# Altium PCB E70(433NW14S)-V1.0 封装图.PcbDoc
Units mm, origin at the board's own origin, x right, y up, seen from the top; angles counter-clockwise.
Board outline 26 x 16 mm, 2 copper layers (Top Layer, Bottom Layer); 5 components, 52 nets, 42 pads, 0 vias.
Unrouted connection lines stored in the file: 4.
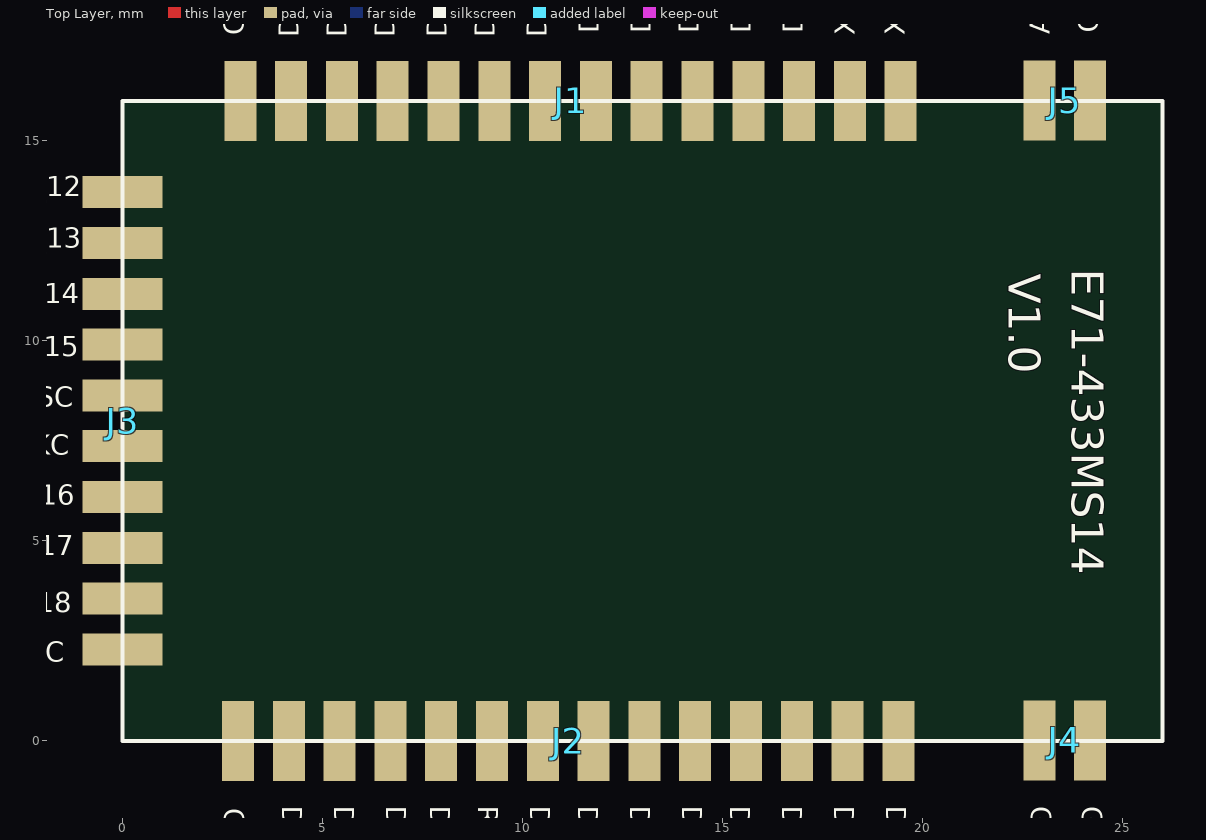
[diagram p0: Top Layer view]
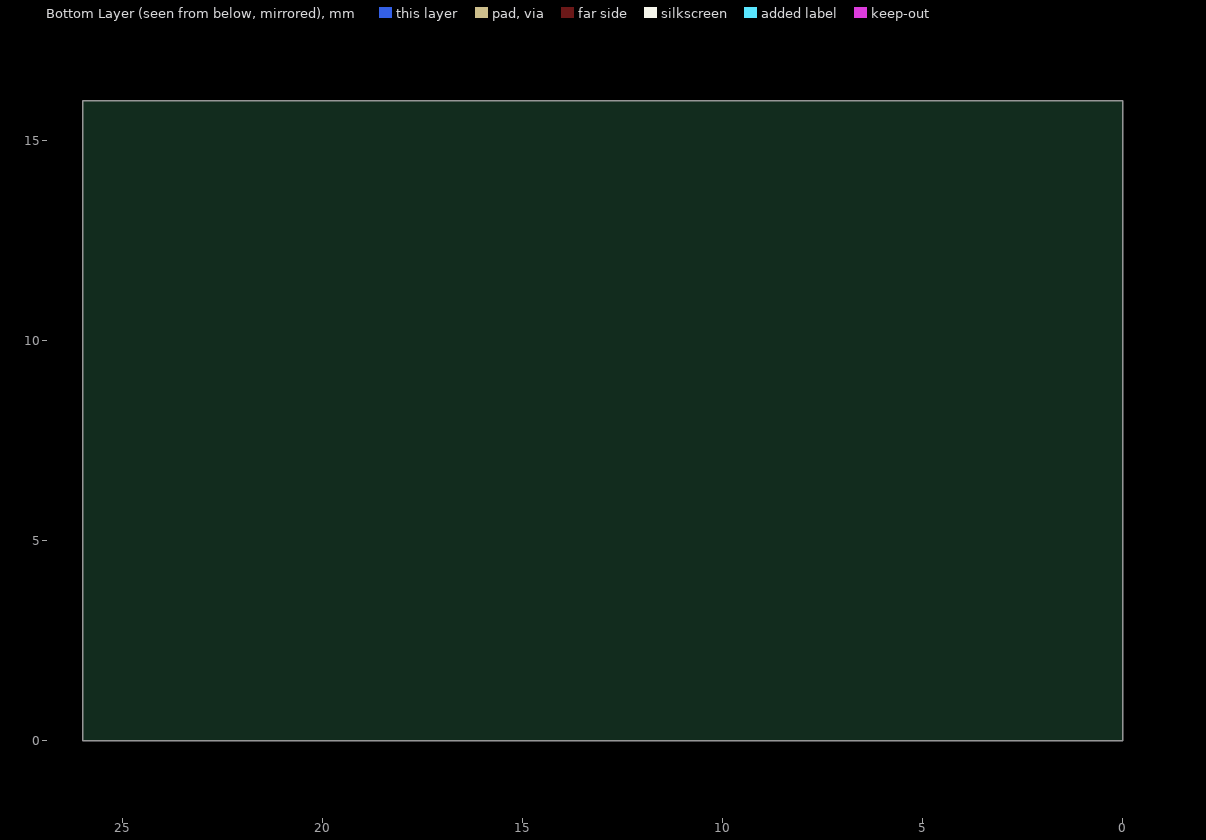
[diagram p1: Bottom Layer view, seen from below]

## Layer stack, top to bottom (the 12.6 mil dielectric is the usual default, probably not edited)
Top Layer: signal copper 0.0356
Dielectric: core 0.32, FR-4, Dk 4.8
Bottom Layer: signal copper 0.0356

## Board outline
0,0 26,0 26,16 0,16

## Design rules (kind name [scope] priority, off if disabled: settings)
Clearance [All] p1: gap=0.152
PolygonConnect [All] p1: connectstyle=Direct reliefconductorwidth=0.254 reliefentries=4 polygonreliefangle="90 Angle"
RoutingVias [All] p1: holewidth=0.711 width=1.27 viastyle="Through Hole" minholewidth=0.711 minwidth=1.27 maxholewidth=0.711 maxwidth=1.27
SilkscreenOverComponentPads [All] p1: minsilkscreentomaskgap=0.254
SolderMaskExpansion [All] p1: expansion=0.102
Width [All] p1: maxlimit=1 minlimit=0.18 preferedwidth=0.254 minimp=50.000000 maximp=50.000000 favimp=50.000000
27 further rules are at their usual default settings.

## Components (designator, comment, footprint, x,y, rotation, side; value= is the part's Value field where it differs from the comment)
J1 "Header 14H" 14P-1.27MM#1 11.2,16 r270 top
J2 "Header 14H" 14P-1.27MM#2 11.142,-0.001 r90 top
J3 "Header 10H" 10P-1.27MM 0,8 r0 top
J4 "Header 2H" 2P-1.27B#1 24.26,0 r90 top
J5 "Header 2H" 2P-1.27B#2 24.26,15.996 r90 top

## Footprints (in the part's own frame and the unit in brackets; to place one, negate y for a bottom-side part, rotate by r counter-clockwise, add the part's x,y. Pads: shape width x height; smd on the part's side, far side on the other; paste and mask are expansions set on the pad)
2P-1.27B#1 [mm]
  rect 2x0.8 smd: 41(0.01,1.34) 42(0.01,0.07)
2P-1.27B#2 [mm]
  rect 2x0.8 smd: 1(0.01,0.07) 2(0.01,1.34)
10P-1.27MM [mm]
  rect 2x0.8 smd: 17(0,5.715) 18(0,4.445) 19(0,3.175) 20(0,1.905) 21(0,0.635) 22(0,-0.635) 23(0,-1.905) 24(0,-3.175) 25(0,-4.445) 26(0,-5.715)
14P-1.27MM#1 [mm]
  rect 2x0.8 smd: 3(0,8.255) 4(0,6.985) 5(0,5.715) 6(0,4.445) 7(0,3.175) 8(0,1.905) 9(0,0.635) 10(0,-0.635) 11(0,-1.905) 12(0,-3.175) 13(0,-4.445) 14(0,-5.715) 15(0,-6.985) 16(0,-8.255)
14P-1.27MM#2 [mm]
  rect 2x0.8 smd: 27(0,8.255) 28(0,6.985) 29(0,5.715) 30(0,4.445) 31(0,3.175) 32(0,1.905) 33(0,0.635) 34(0,-0.635) 35(0,-1.905) 36(0,-3.175) 37(0,-4.445) 38(0,-5.715) 39(0,-6.985) 40(0,-8.255)

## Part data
J1 J2: "Header, 14-Pin, Right Angle"
J3: "Header, 10-Pin, Right Angle"
J4 J5: "Header, 2-Pin, Right Angle"

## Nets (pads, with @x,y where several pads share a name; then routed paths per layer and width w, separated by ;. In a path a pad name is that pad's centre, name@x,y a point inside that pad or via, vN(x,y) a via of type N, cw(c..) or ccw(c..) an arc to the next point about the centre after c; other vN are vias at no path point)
ANT1: J5.2
DCDC-SW: 
DIO_1: J1.5
DIO_2: J1.6
DIO_3: J1.7
DIO_4: J1.8
DIO_5: J1.9
DIO_6: J1.10
DIO_7: J1.11
DIO_8: J1.12
DIO_9: J1.13
DIO_10: J1.14
DIO_11: J1.15
DIO_12: J3.17
DIO_13: J3.18
DIO_14: 
DIO_15: 
DIO_16: J3.23
DIO_17: J3.24
DIO_18: J3.25
DIO_19: J2.28
DIO_20: J2.29
DIO_21: J2.30
DIO_22: J2.31
DIO_23: J2.33
DIO_24: J2.34
DIO_25: J2.35
DIO_26: J2.36
DIO_27: J2.37
DIO_28: J2.38
DIO_29: J2.39
DIO_30: J2.40
GND: J1.16 J2.27 J4.41 J4.42 J5.1
JTAG_TCK: J3.22
JTAG_TMS: J3.21
NetC1_1: 
NetC6_2: 
NetC7_1: 
NetC7_2: 
NetC8_2: 
NetC11_1: 
NetC13_2: 
NetC17_1: 
NetJ3_3: J3.19
NetJ3_4: J3.20
NetU1_46: 
NetU1_47: 
RESET: J2.32
VCC: J3.26
VDD: 
X32K_Q1: J1.3
X32K_Q2: J1.4

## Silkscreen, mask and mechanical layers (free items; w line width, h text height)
Top Overlay:
  the board outline again, w0.1
  text "GND" at 24.396,17.705 h0.5 r90
  text "DIO_5" at 11.903,17.682 h0.5 r90
  text "DIO_4" at 13.203,17.682 h0.5 r90
  text "DIO_3" at 14.403,17.682 h0.5 r90
  text "DIO_2" at 15.703,17.682 h0.5 r90
  text "DIO_1" at 17.003,17.682 h0.5 r90
  text "ANT" at 23.175,17.66 h0.5 r90
  text "GND" at 3.034,17.632 h0.5 r90
  text "X32K_Q2" at 18.303,17.632 h0.5 r90
  text "X32K_Q1" at 19.553,17.632 h0.5 r90
  text "DIO_11" at 4.403,17.582 h0.5 r90
  text "DIO_10" at 5.603,17.582 h0.5 r90
  text "DIO_9" at 6.803,17.582 h0.5 r90
  text "DIO_8" at 8.103,17.582 h0.5 r90
  text "DIO_7" at 9.303,17.582 h0.5 r90
  text "DIO_6" at 10.603,17.582 h0.5 r90
  text "DIO_12" at -3.536,13.619 h0.5
  text "DIO_13" at -3.536,12.321 h0.5
  text "E71-433MS14" at 23.734,11.796 h0.8 r270
  text "V1.0" at 22.16,11.677 h0.8 r270
  text "DIO_14" at -3.579,10.937 h0.5
  text "DIO_15" at -3.588,9.612 h0.5
  text "TMSC" at -3.166,8.346 h0.5
  text "TCKC" at -3.166,7.146 h0.5
  text "DIO_16" at -3.699,5.903 h0.5
  text "DIO_17" at -3.721,4.637 h0.5
  text "DIO_18" at -3.766,3.215 h0.5
  text "VCC" at -2.899,1.971 h0.5
  text "DIO_19" at 3.988,-1.625 h0.5 r270
  text "DIO_20" at 5.288,-1.625 h0.5 r270
  text "DIO_21" at 6.588,-1.625 h0.5 r270
  text "DIO_22" at 7.688,-1.625 h0.5 r270
  text "RESET" at 8.888,-1.625 h0.5 r270
  text "DIO_23" at 10.188,-1.625 h0.5 r270
  text "DIO_24" at 11.388,-1.625 h0.5 r270
  text "DIO_25" at 12.688,-1.625 h0.5 r270
  text "DIO_26" at 13.988,-1.625 h0.5 r270
  text "DIO_27" at 15.188,-1.625 h0.5 r270
  text "DIO_28" at 16.488,-1.625 h0.5 r270
  text "DIO_29" at 17.788,-1.625 h0.5 r270
  text "DIO_30" at 19.088,-1.625 h0.5 r270
  text "GND" at 22.724,-1.638 h0.5 r270
  text "GND" at 23.995,-1.638 h0.5 r270
  text "GND" at 2.548,-1.685 h0.5 r270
